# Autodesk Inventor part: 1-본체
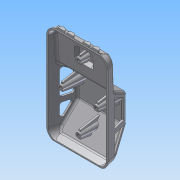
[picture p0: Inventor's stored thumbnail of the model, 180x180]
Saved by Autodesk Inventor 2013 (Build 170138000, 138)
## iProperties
Created: 2015-05
Part Number: 1-본체
Material: ABS 플라스틱
Document SubType Name: Modeling
Designer: Administrator
Density: 7.85 g/cm^3
Mass: 247.181 g
Surface Area: 309.221 cm^2
Volume: 31.488 cm^3
Author: Administrator
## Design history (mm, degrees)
sketch "스케치1"
  geometry: L1 (-38, 15.5)-(38, 15.5); L2 (38, 15.5)-(38, -15.5); L3 (38, -15.5)-(-38, -15.5); L4 (-38, -15.5)-(-38, 15.5); L5 (-38, 15.5)-(38, -15.5); L6 (38, 15.5)-(-38, -15.5); L7 (38, -15.5)-(29.694, 15.5); L8 (-38, -15.5)-(-29.694, 15.5); 1 further point
  constraints: 16 end point, 2 midpoint, 2 parallel, 2 point on line, 1 horizontal, 1 perpendicular
  dimensions: "d2" = 31 distance between parallel lines of L3 L1; "d4" = 76 distance of L1.start L1.end; "d5" = 105 deg angle of L3 L8; "d6" = 105 deg angle of L3 L7
extrude "돌출1" new body sketch "스케치1" distance "d7" = 122; taper "d8" = 0 deg
node "작업 평면1"
fillet "모깎기1" dims "d97" = 12
sketch "스케치2"
  geometry: L1 (15.5, 12)-(15.5, 110) reference; L2 (-15.5, 12)-(-15.5, 110) reference; L3 (-14.5, 122)-(-14.5, 121); L4 (-14.5, 121)-(-15.5, 121); L5 (-15.5, 1)-(-14.5, 1); L6 (-14.5, 1)-(-14.5, 0); L7 (-14.5, 122)-(-6.5, 119.856); L8 (-6.5, 119.856)-(-4.411, 80); L9 (-4.411, 80)-(15.5, 67.558); L10 (15.5, 67.558)-(15.5, 32.679); L11 (15.5, 32.679)-(-4.5, 2.679); L12 (-4.5, 2.679)-(-14.5, 0); L13 (15.5, 12)-(-15.5, 12) reference; L14 (-15.5, 110)-(15.5, 110) reference; L15 (15.5, 122)-(-15.5, 122) reference; L16 (-15.5, 0)-(15.5, 0) reference; L17 (15.5, 12)-(15.5, 110) reference; L18 (15.5, 12)-(15.5, 0) reference; L19 (15.5, 122)-(15.5, 110) reference; L20 (-15.5, 110)-(-15.5, 122) reference; L21 (-15.5, 0)-(-15.5, 12) reference; L22 (-15.5, 1)-(-15.5, 0); L23 (-15.5, 0)-(-14.5, 0); L24 (-15.5, 121)-(-15.5, 122); L25 (-15.5, 122)-(-14.5, 122); 1 further point
  constraints: 28 end point, 6 point on line, 4 collinear, 2 parallel, 2 perpendicular
  dimensions: "d10" = 1 distance of L3.start L3.end; "d12" = 1 distance of L3.end L4.end; "d13" = 1 distance of L5.start L5.end; "d14" = 1 distance of L5.end L6.end; "d15" = 105 deg angle of L2 L12; "d16" = 105 deg angle of L2 L7; "d17" = 9 distance from line of L2 L7.end; "d18" = 125 deg angle of L9 L8; "d19" = 42 vertical distance of L8.end L3.start; "d21" = 3 deg angle of L2 L8; "d22" = 30 vertical distance of L10.end L11.end; "d23" = 20 horizontal distance of L10.end L11.end
  node "투영된 루프1"
extrude "돌출2" cut sketch "스케치2" stored distance "d24" = 122; taper "d25" = 0 deg
sketch "스케치4"
  geometry: L1 (22.588, 8.441)-(48.588, 8.441); L2 (48.588, 8.441)-(48.588, 28.441); L3 (48.588, 28.441)-(22.588, 28.441); L4 (22.588, 28.441)-(22.588, 8.441); L5 (22.588, 8.441)-(48.588, 28.441); L6 (48.588, 8.441)-(22.588, 28.441); L7 (60.897, -2.559)-(10.28, -2.559) reference; 5 further points
  constraints: 12 end point, 3 midpoint, 2 parallel, 1 horizontal, 1 perpendicular, 1 vertical alignment
  dimensions: "d31" = 26 distance of L2.end L3.end; "d33" = 20 distance of L1.end L2.end; "d34" = 11 distance between parallel lines of L7 L1
extrude "돌출4" join sketch "스케치4" distance "d35" = 5; taper "d36" = -20 deg
feature "쉘1" dims "d28" = 2
extrude "돌출3" cut sketch "스케치2" stored distance "d29" = 1; taper "d30" = 0 deg
sketch "스케치5"
  geometry: L1 (-4.5, 74.16)-(10.5, 64.787); L2 (10.5, 64.787)-(10.5, 40.16); L3 (10.5, 40.16)-(-4.5, 40.16); L4 (-4.5, 40.16)-(-4.5, 74.16); L5 (15.5, 32.679)-(15.5, 67.558) reference; L6 (15.5, 67.558)-(-4.411, 80) reference; L7 (1.714, 12)-(15.5, 32.679) reference; L8 (10.5, 34.193)-(-4.5, 34.193); L9 (-4.5, 34.193)-(-4.5, 11.693); L10 (-4.5, 11.693)-(10.5, 34.193); 2 further points
  constraints: 14 end point, 4 perpendicular, 2 parallel, 1 vertical
  dimensions: "d39" = 34 distance of L3.end L1.start; "d41" = 15 distance of L2.end L3.end; "d42" = 5 distance between parallel lines of L5 L2; "d45" = 5 distance between parallel lines of L6 L1; "d46" = 15 distance of L8.start L8.end; "d47" = 5 distance from line of L5 L8.start; "d48" = 5 distance between parallel lines of L7 L10
extrude "돌출5" cut sketch "스케치5" stored distance "d49" = 1; taper "d50" = 0 deg
node "작업 평면2"
sketch "스케치6"
  geometry: L1 (12.691, -1)-(63.309, -1) reference; L2 (7.458, 0)-(68.542, 0) reference; C1 r 3 at (38, 20); C2 r 3 at (16, 60); C3 r 3 at (60, 60); C4 r 3 at (38, 100); 6 further points
  constraints: 4 centre point, 3 equal radius, 2 vertical alignment, 1 horizontal alignment, 1 midpoint
  dimensions: "d52" = 21 distance from line of L1 C1.centre; "d53" = 40 vertical distance of C1.centre C3.centre; "d54" = 40 vertical distance of C3.centre C4.centre; "d55" = 6 diameter of C4; "d56" = 44 distance of C3.centre C2.centre; "d57" = 22 horizontal distance of C1.centre C2.centre
extrude "돌출6" join sketch "스케치6" stored distance "d58" = 30; taper "d59" = 4 deg
sketch "스케치7"
  geometry: L1 (-2.184, 94.828)-(-2.894, 108.368) reference; L2 (-14.5, 104)-(-2.708, 104.825) reference; L3 (-14.5, 98)-(-2.306, 97.147) reference; L4 (-14.5, 24)-(8.376, 25.6) reference; L5 (-14.5, 18)-(2.517, 16.81) reference; L6 (-0.69, 12)-(13.5, 33.285) reference; L7 (-14.5, 18)-(-14.5, 24) reference; L8 (-14.5, 98)-(-14.5, 104) reference; L9 (-12.5, 106)-(-12.5, 96); L10 (-12.5, 106)-(-1.472, 107.944); L11 (-1.472, 107.944)-(-1.472, 94.056); L12 (-1.472, 94.056)-(-12.5, 96); L13 (-12.5, 26)-(-12.5, 16); L14 (-12.5, 16)-(0.399, 13.634); L15 (11.332, 30.033)-(-12.5, 26); L16 (11.332, 30.033)-(0.399, 13.634); 6 further points
  constraints: 16 end point, 4 midpoint, 2 horizontal alignment, 2 parallel, 2 point on line, 1 collinear, 1 equal length, 1 vertical
  dimensions: "d60" = 20 deg angle of L12 L10; "d61" = 2 distance between parallel lines of L8 L9; "d62" = 10 distance of L9.start L9.end; "d64" = 13.88898 distance of L10.end L11.end; "d65" = 20 deg angle of L14 L15; "d66" = 2 distance between parallel lines of L7 L13; "d67" = 10 distance of L13.start L13.end; "d68" = 46.7058 deg angle of L16 L15
extrude "돌출7" join sketch "스케치7" stored distance "d69" = 2; taper "d70" = 0 deg
node "작업 평면3"
sketch "스케치8"
  geometry: L1 (13.5, 33.285)-(13.5, 66.449) reference; L2 (-14.5, 58)-(-14.5, 64) reference; L3 (13.5, 56.042)-(13.5, 65.958) reference; L4 (-14.5, 58)-(13.5, 56.042) reference; L5 (-14.5, 64)-(13.5, 65.958) reference; L6 (-12.5, 66)-(-12.5, 56); L7 (-12.5, 56)-(13.5, 51.415); L8 (8.339, 69.674)-(-12.5, 66); L9 (13.5, 66.449)-(-6.354, 78.856) reference; L10 (-12.5, 61)-(20.878, 61); 2 further points
  constraints: 8 end point, 2 midpoint, 2 point on line, 1 horizontal alignment, 1 parallel, 1 perpendicular
  dimensions: "d72" = 20 deg angle of L7 L8; "d73" = 2 distance between parallel lines of L2 L6; "d74" = 10 distance of L6.start L6.end; "d75" = 10 deg angle of L7 L10
extrude "돌출8" join sketch "스케치8" stored distance "d76" = 2; taper "d77" = 0 deg
sketch "스케치9"
  geometry: C1 r 3 at (16, 60) reference; C2 r 3 at (60, 60) reference; C3 r 3 at (38, 100) reference; C4 r 3 at (38, 20) reference; 5 further points
  constraints: 4 coincident
hole "구멍1" sketch "스케치9" at (16, 60), (60, 60), (38, 100), (38, 20) diameter "d78" = 3.242; stored, may be unused: countersink angle "d82" = 90 deg, drill point angle "d84" = 118 deg; dims "d79" = 9, "d80" = 4, "d81" = 2, "d83" = 11
sketch "스케치10"
  geometry: L1 (4.385, 32.679)-(55.002, 32.679) reference; 4 further points
  constraints: 1 vertical alignment, 1 other
  dimensions: "d85" = 50 distance from line of L1 point (29.694, -17.321)
feature "엠보싱1" sketch "스케치10" dims "d2" = 31, "d4" = 76, "d5" = 105 deg, "d6" = 105 deg, "d17" = 9, "d86" = 0.5, "d87" = 0
node "작업 평면4"
sketch "스케치11"
  geometry: A1 r 4 centre (-21, -14.5) between (-17, -14.5) and (-25, -14.5); A2 r 4 centre (-10, -14.5) between (-6, -14.5) and (-14, -14.5); A3 r 4 centre (10, -14.5) between (14, -14.5) and (6, -14.5); A4 r 4 centre (21, -14.5) between (25, -14.5) and (17, -14.5); 5 further points
  constraints: 8 point on circle, 4 centre point, 3 equal radius, 13 other
  dimensions: "d89" = 11 distance of A4.centre A3.centre; "d91" = 11 distance of A2.centre A1.centre; "d92" = 20 distance of A3.centre A2.centre; "d93" = 4 radius of A1; "d94" = 10 horizontal distance of point (0, 0) A2.centre
extrude "돌출9" join sketch "스케치11" stored distance "d95" = 2; taper "d96" = 0 deg
fillet "모깎기2" dims "d98" = 3
fillet "모깎기3" dims "d99" = 3
fillet "모깎기4" dims "d100" = 3
node "솔리드1"
mirror "대칭1"
node "투영된 루프3"
node "투영된 루프4"
node "투영된 루프5"
other parameters: "d9" = 38, "d51" = -1, "d71" = 22, "d88" = 124
